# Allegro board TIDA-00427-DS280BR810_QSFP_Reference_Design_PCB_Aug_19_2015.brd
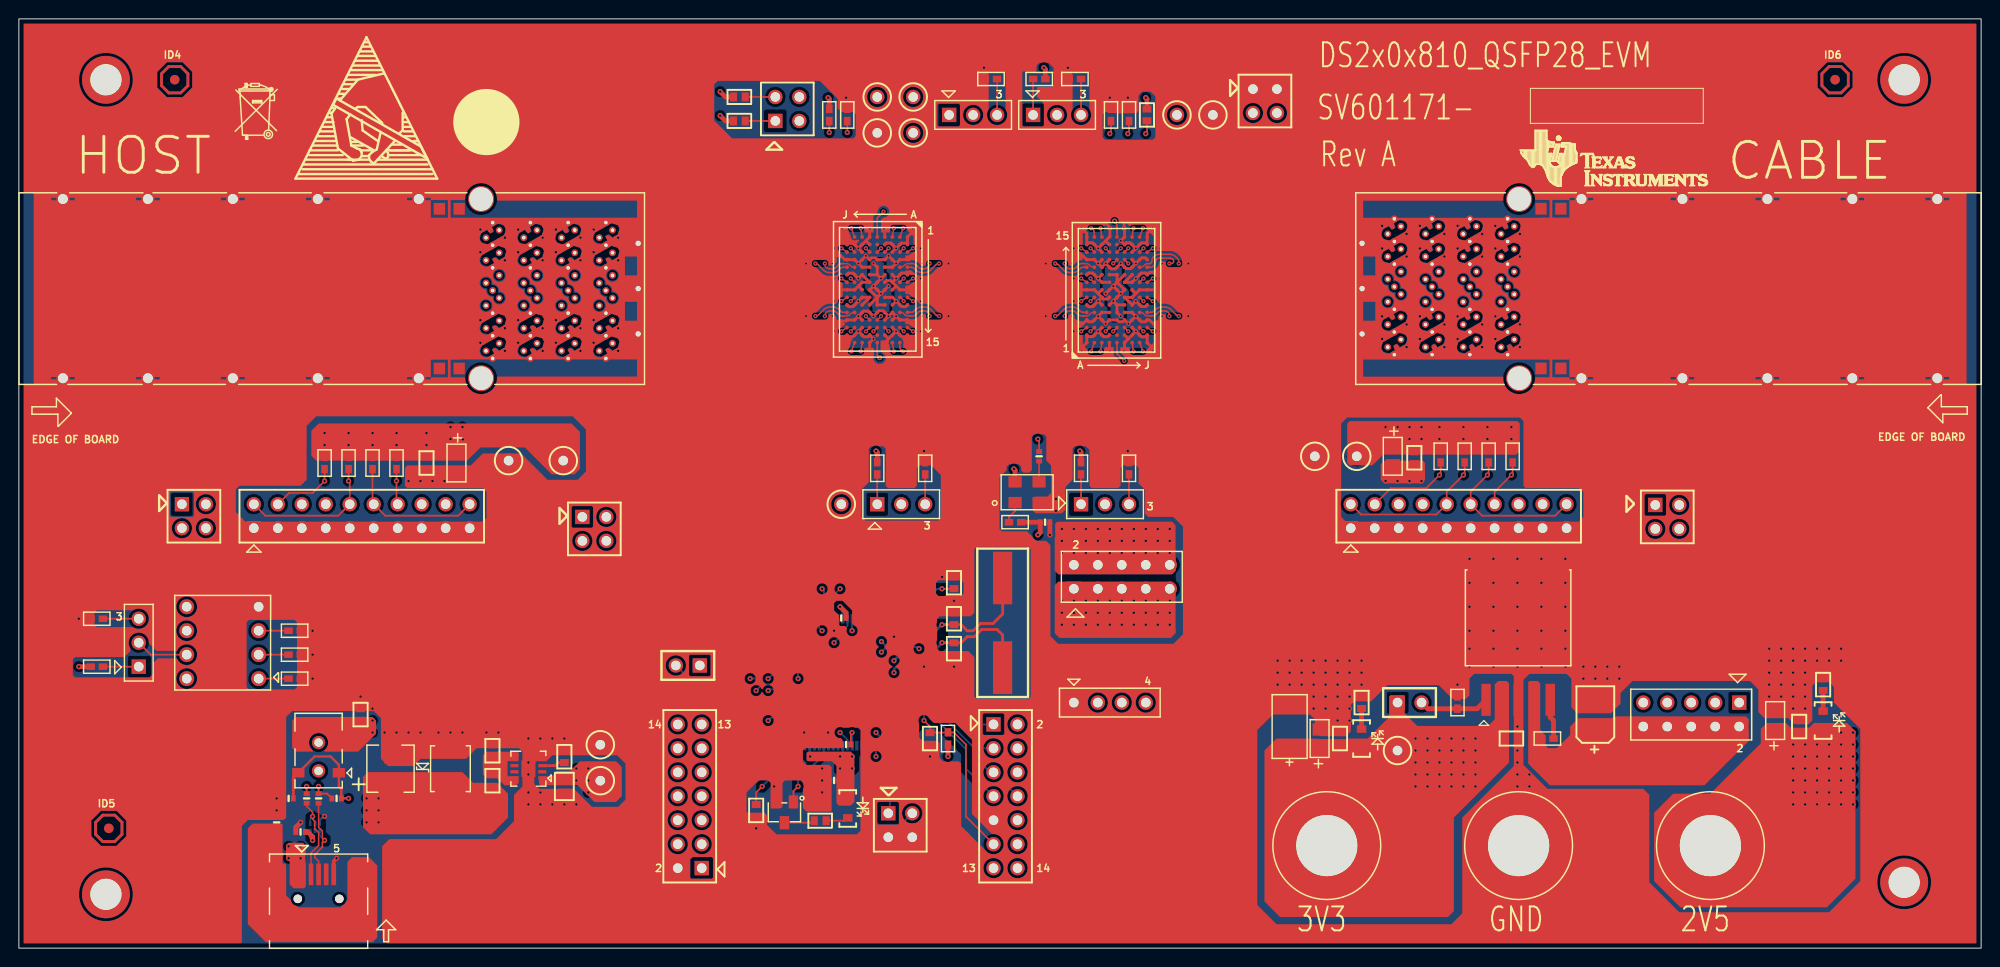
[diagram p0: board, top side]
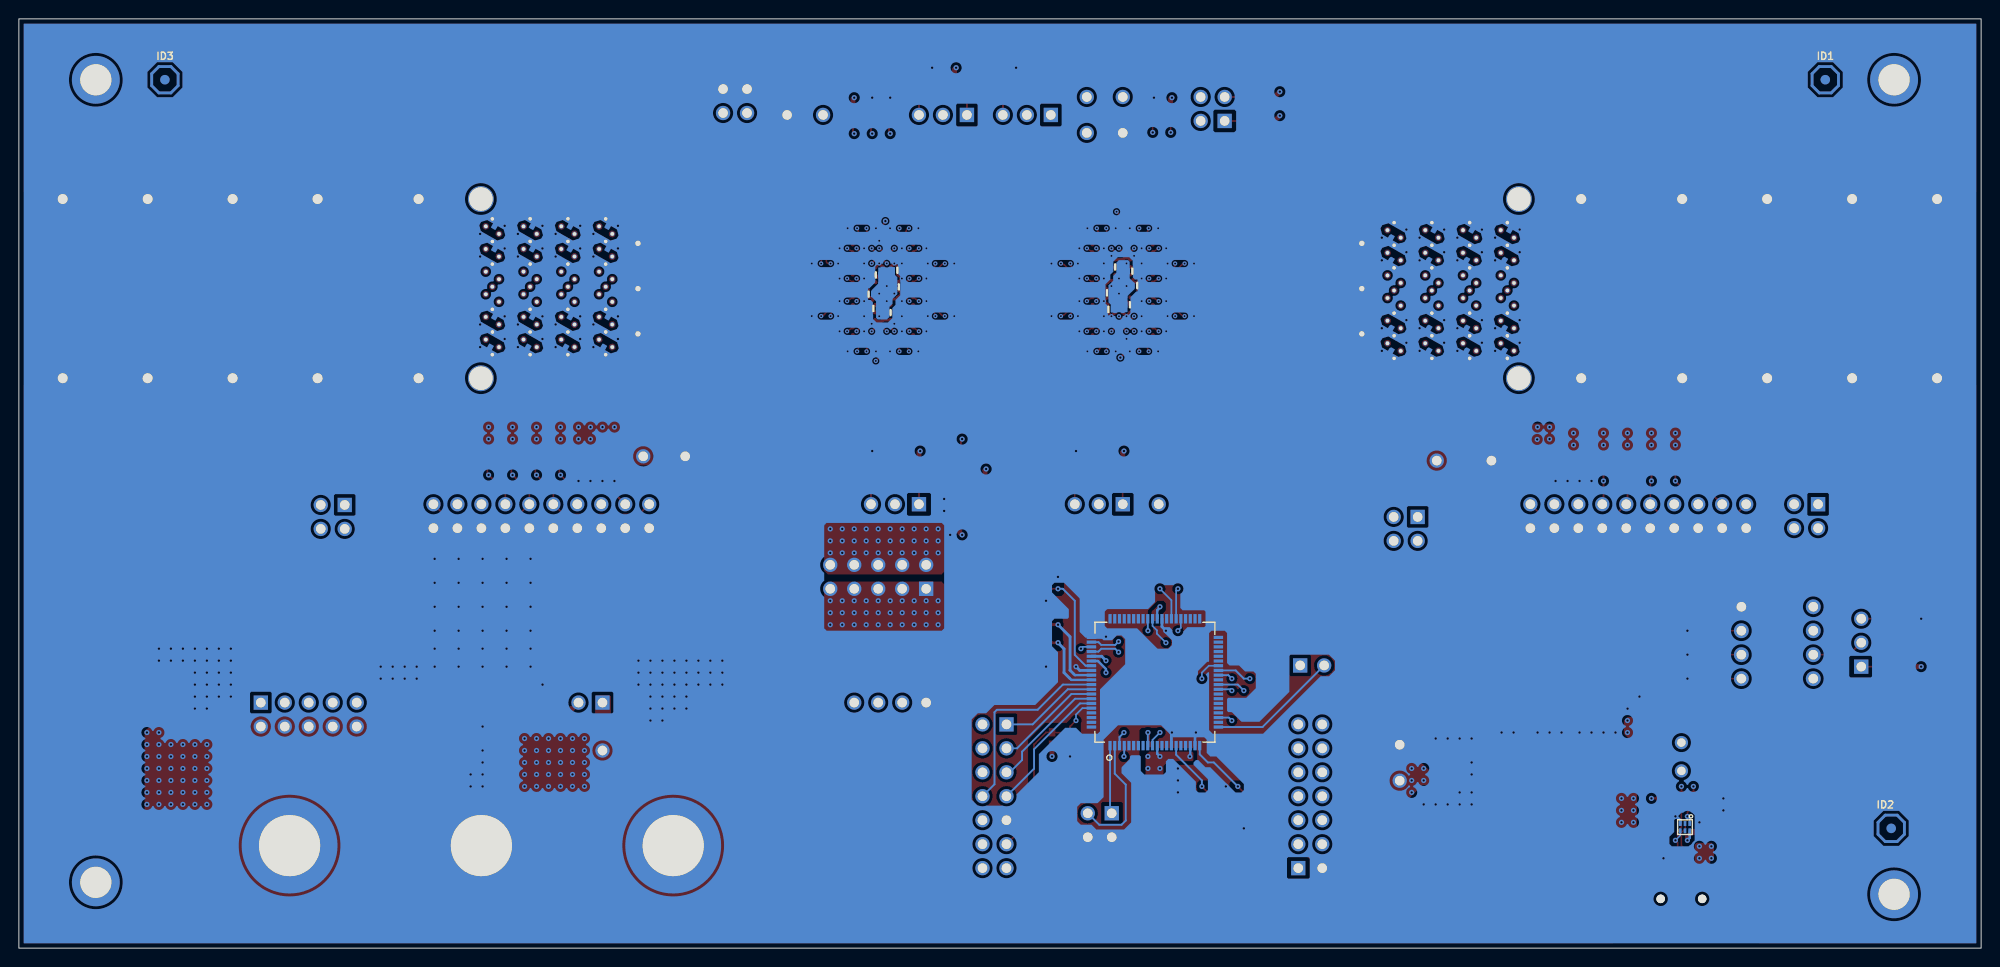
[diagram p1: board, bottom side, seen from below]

Outline 207.87 x 98.53 mm; copper layers: TOP, ART02, GND03, ART04, GND05, POWER06, POWER07, GND08, ART09, GND10, ART11, BOTTOM. Coordinates in mm from the lower left corner of the outline.
Outline path: rectangle 0,0 207.87,98.53

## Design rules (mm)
net group DIFF90: nets DM DP N16782058 N16782064 RXN0_CABLE_BOT RXN0_CABLE_TOP RXN0_HOST_BOT RXN0_HOST_TOP RXN1_CABLE_BOT RXN1_CABLE_TOP RXN1_HOST_BOT RXN1_HOST_TOP RXN2_CABLE_BOT RXN2_CABLE_TOP RXN2_HOST_BOT RXN2_HOST_TOP RXN3_CABLE_BOT RXN3_CABLE_TOP RXN3_HOST_BOT RXN3_HOST_TOP RXP0_CABLE_BOT RXP0_CABLE_TOP RXP0_HOST_BOT RXP0_HOST_TOP RXP1_CABLE_BOT RXP1_CABLE_TOP RXP1_HOST_BOT RXP1_HOST_TOP RXP2_CABLE_BOT RXP2_CABLE_TOP RXP2_HOST_BOT RXP2_HOST_TOP RXP3_CABLE_BOT RXP3_CABLE_TOP RXP3_HOST_BOT RXP3_HOST_TOP TXN0_CABLE_BOT TXN0_CABLE_TOP TXN0_HOST_BOT TXN0_HOST_TOP TXN1_CABLE_BOT TXN1_CABLE_TOP TXN1_HOST_BOT TXN1_HOST_TOP TXN2_CABLE_BOT TXN2_CABLE_TOP TXN2_HOST_BOT TXN2_HOST_TOP TXN3_CABLE_BOT TXN3_CABLE_TOP TXN3_HOST_BOT TXN3_HOST_TOP TXP0_CABLE_BOT TXP0_CABLE_TOP TXP0_HOST_BOT TXP0_HOST_TOP TXP1_CABLE_BOT TXP1_CABLE_TOP TXP1_HOST_BOT TXP1_HOST_TOP TXP2_CABLE_BOT TXP2_CABLE_TOP TXP2_HOST_BOT TXP2_HOST_TOP TXP3_CABLE_BOT TXP3_CABLE_TOP TXP3_HOST_BOT TXP3_HOST_TOP
net group POWER: nets GND N16782035 QSFP_VCC_3P3V VBUS VDD_2P5V VDD_2P5V_REG VDD_2P5V_REG_ENABLE_ VDD_3P3V VDD_3P3V_USB

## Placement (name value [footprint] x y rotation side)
C1  0.1 uF  [C_0402]  90.17 68.22 0 bottom
C2  0.1 uF  [C_0402]  89.92 71.78 0 bottom
C3  0.1 uF  [C_0402]  89.41 70.26 0 bottom
C4  0.1 uF  [C_0402]  91.74 72.22 180 bottom
C14  1 uF  [C_0402]  92.46 67.72 180 bottom
C15  0.1 uF  [C_0402]  114.65 70.11 0 bottom
C16  0.1 uF  [C_0402]  117.86 69.34 180 bottom
C17  0.1 uF  [C_0402]  115.53 67.38 0 bottom
C18  0.1 uF  [C_0402]  117.09 71.37 180 bottom
C28  1 uF  [C_0402]  117.35 67.82 180 bottom
C29  0.1 uF  [C_0402]  87.63 21.59 0 top
C30  2.2 nF  [C_0603]  96.52 22.23 270 top
C31  30 pF  [C_0603]  99.06 31.75 90 top
C32  30 pF  [C_0603]  99.06 34.92 270 top
C33  0.1 uF  [C_0402]  87.12 35 0 top
C34  0.47 uF  [C_0603]  78.11 14.61 270 top
C35  0.1 uF  [C_0402]  86.36 17.78 0 top
C36  0.1 uF  [C_0402]  29.84 12.32 0 top
C37  220 pF  [C_0603]  36.2 24.77 270 top
C38  22 uF  [CODE_B]  39.37 19.02 0 top
C39  1 uF  [C_0603]  50.16 20.93 270 top
C40  0.01 uF  [C_0603]  57.78 20.29 270 top
C41  2.2 uF  [C_0805]  57.78 17.14 90 top
C42  220 pF  [C_0603]  99.06 38.73 270 top
C43  0.1 uF  [C_0402]  108.71 45.16 180 top
C44  1 uF  [C_0603]  158.12 22.23 180 top
C45  47 uF  [C_1210]  167 24.77 90 top
C46  10 uF  [C_0805_TANT]  137.79 22.23 90 top
C47  1 uF  [C_0603]  139.95 22.23 270 top
C48  22 uF  [C_SIZEC]  134.62 23.5 90 top
C49  10 uF  [C_0805_TANT]  186.06 24.13 90 top
C50  1 uF  [C_0603]  188.59 23.5 90 top
C51  1 uF  [C_0603]  43.18 51.44 90 top
C52  10 uF  [C_0805_TANT]  46.35 51.44 270 top
C53  10 uF  [C_0805_TANT]  145.54 52.15 270 top
C54  1 uF  [C_0603]  147.83 51.99 90 top
C55  1 uF  [C_0402]  92.61 69.48 180 bottom
C56  1 uF  [C_0402]  114.81 71.88 0 bottom
D1  RED-LED  [LED_FOOTPRINT]  87.81 14.81 270 top
D2  1SMB5922BTS  [SMB]  45.72 19.02 90 top
D3  RED-LED  [LED_FOOTPRINT]  142.24 22.23 90 top
D4  RED-LED  [LED_FOOTPRINT]  191.13 24.13 90 top
FB1  BK1608HS600-T  [FB0603]  50.16 17.75 90 top
J1  HEADER 2X2  [HEADER_2X2]  92.1 14.3 270 top
J2  HEADER 7X2  [HEADER_7X2]  103.25 23.72 270 top
J3  HEADER 2X2  [HEADER_2X2]  59.69 45.72 270 top
J4  HEADER 1x4  [4_HEADER]  115.57 26.04 0 top
J5  HEADER 1x2  [CN-HDR1X2]  72.14 29.97 180 top
J6  USB_Conn_1734035-2  [1734035-2]  31.75 -0.03 0 top
J7  HEADER 5x2/SM_1  [CN-HDR2X5]  116.84 39.37 0 top
J8  HEADER, 2-PIN  [CN-HDR1X2]  146.05 26.04 0 top
J9  Binding Post, Keystone 7007, Black  [CN-BANANAJK-275-INTERFACE]  158.88 10.87 0 top
J10  Binding Post, Keystone 7006, Red  [CN-BANANAJK]  138.56 10.87 0 top
J11  Binding Post, Keystone 7006, Red  [CN-BANANAJK]  179.2 10.87 0 top
J12  HEADER 5x2/SM_1  [CN-HDR2X5]  177.16 24.77 180 top
J13  HEADER 10x2/SM  [HEADER_10X2_SM]  24.89 44.53 0 top
J14  HEADER 10x2/SM  [HEADER_10X2_SM]  141.1 44.53 0 top
J15  HEADER 7X2  [HEADER_7X2]  72.34 8.48 90 top
J16  HEADER 3  [3_HEADER]  109.98 88.34 0 top
J17  HEADER 3  [3_HEADER]  101.09 88.34 0 top
J18  4808-3004-CP  [DIP8]  21.59 32.38 90 top
J19  HEADER 3  [3_HEADER]  12.7 32.38 90 top
J20  HEADER 3  [3_HEADER]  93.47 47.07 0 top
J21  HEADER 3  [3_HEADER]  115.06 47.07 0 top
J22  HEADER 2X2  [HEADER_2X2]  80.14 87.71 0 top
J23  HEADER 2X2  [HEADER_2X2]  17.27 47.07 270 top
J24  HEADER 2X2  [HEADER_2X2]  173.35 46.99 270 top
J25  HEADER 2X2  [HEADER_2X2]  130.73 91.08 270 top
NOREF  -  []  37.33 86.03 0 top
NOREF#2  VAL ASSEMBLY  [unnamed#2]  9.22 5.71 0 top
NOREF#3  VAL ASSEMBLY  [unnamed#2]  199.72 92.07 0 top
NOREF#4  -  [unnamed#3]  192.41 92.08 0 top
NOREF#5  -  []  50.03 87.81 0 top
NOREF#6  -  []  27.68 88.83 0 top
NOREF#7  VAL ASSEMBLY  [unnamed#2]  199.72 6.98 0 top
NOREF#8  -  [unnamed#3]  16.51 92.08 0 top
NOREF#9  -  []  -137.59 -162.88 0 top
NOREF#10  VAL ASSEMBLY  [unnamed#2]  9.22 92.07 0 top
NOREF#11  -  [unnamed#3]  9.53 12.7 0 top
NOREF#12  -  [unnamed#3]  16.51 92.08 180 bottom
NOREF#13  -  [unnamed#3]  192.41 92.08 180 bottom
NOREF#14  -  [unnamed#3]  9.53 12.7 180 bottom
Q1  BSS138  [SOT-23]  81.1 14.4 180 top
R7  1k  [0402]  115.7 88.34 270 top
R8  1k  [0402]  117.6 88.34 270 top
R11  1k  [0402]  108.09 92.15 0 top
R12  2.0K  [RR0603]  119.51 88.34 270 top
R15  2.0K  [RR0603]  76.33 87.71 180 top
R19  1k  [0402]  111.87 92.15 0 top
R22  2.0K  [RR0603]  76.33 90.25 180 top
R23  1k  [0402]  87.76 88.34 270 top
R24  1k  [0402]  85.85 88.34 270 top
R25  33 k  [R_0402]  98.42 22.23 270 top
R26  200  [RES_HDC-0603]  84.89 13.51 180 top
R27  1k  [0402]  29.21 33.66 180 top
R28  33  [RES_HDC-0402]  30.48 15.88 90 top
R29  33  [RES_HDC-0402]  31.75 15.88 90 top
R30  1.5K  [RES_HDC-0402]  33.66 15.88 0 top
R31  33K  [RES_HDC-0402]  27.3 13.34 90 top
R32  1.2M  [RES_HDC-0402]  28.57 15.88 0 top
R33  4.7K  [R_0402]  105.54 45.16 0 top
R34  33  [RES_HDC-0402]  108.08 52.15 90 top
R35  10K  [R_0402]  152.4 26.04 90 top
R36  10K  [R_0402]  161.93 22.23 0 top
R37  750  [RES_HDC-0603]  142.24 26.04 90 top
R38  360  [RES_HDC-0603]  191.13 27.94 270 top
R39  4.7K  [R_0402]  40.01 51.44 90 top
R40  4.7K  [R_0402]  37.47 51.44 90 top
R41  4.7K  [R_0402]  32.38 51.44 90 top
R42  4.7K  [R_0402]  34.92 51.44 90 top
R43  4.7K  [R_0402]  158.24 52.15 90 top
R44  4.7K  [R_0402]  155.7 52.15 90 top
R45  4.7K  [R_0402]  150.62 52.15 90 top
R46  4.7K  [R_0402]  153.16 52.15 90 top
R47  1k  [0402]  102.98 92.15 0 top
R48  1k  [0402]  29.21 31.11 180 top
R49  1k  [0402]  29.21 28.57 180 top
R50  1k  [0402]  8.26 29.84 180 top
R51  1k  [0402]  8.26 34.92 0 top
R52  1k  [0402]  90.93 50.88 90 top
R53  1k  [0402]  96.01 50.88 270 top
R54  1k  [0402]  112.52 50.88 90 top
R55  1k  [0402]  117.6 50.88 270 top
S1  -  [EVQPSD02K]  31.75 20.29 90 top
TP1  TEST POINT  [0_100X0_100_INCH]  122.68 88.34 0 top
TP2  TEST POINT  [0_100X0_100_INCH]  126.49 88.34 0 top
TP3  TEST POINT  [0_100X0_100_INCH]  94.74 90.25 0 top
TP4  TEST POINT  [0_100X0_100_INCH]  94.74 86.44 90 top
TP5  TEST POINT  [0_100X0_100_INCH]  90.93 86.44 90 top
TP7  TEST POINT  [0_100X0_100_INCH]  90.93 90.25 0 top
TP8  TEST POINT  [0_100X0_100_INCH]  61.59 17.75 0 top
TP9  TEST POINT  [0_100X0_100_INCH]  61.59 21.56 0 top
TP10  TEST POINT  [0_100X0_100_INCH]  146.05 20.95 90 top
TP11  TEST POINT  [0_100X0_100INCH]  57.67 51.69 270 top
TP12  TEST POINT  [0_100X0_100INCH]  51.88 51.69 270 top
TP13  TEST POINT  [0_100X0_100INCH]  141.73 52.15 90 top
TP14  TEST POINT  [0_100X0_100INCH]  137.29 52.15 90 top
TP15  TEST POINT  [0_100X0_100_INCH]  87.12 47.07 0 top
U1  DS280BR8xx_DS280DF8xx  [DS280BR8XX_DS280DF8XX]  90.93 69.8 270 top
U2  DS280BR8xx_DS280DF8xx  [DS280BR8XX_DS280DF8XX]  116.33 69.8 90 top
U3  Value  [PN80]  87.53 28.19 180 bottom
U4  TPD4E004DRY  [SON-6]  31.37 12.83 0 bottom
U5  TPS73533DRB  [SON-8]  53.98 19.02 90 top
U6  Oscillator, 25 MHz, 2.5V  [TXC_2V5_OSC]  106.81 48.34 0 top
U7  TPS75725  [TO-263]  158.83 31.62 0 top
U8  TE_QSFP28_cage  [MOLEX_ZQSFP_CAGE]  33.15 69.93 0 top
U9  TE_QSFP28_cage  [MOLEX_ZQSFP_CAGE]  174.75 69.93 180 top
Y1  24.0 MHz  [HC49_US]  104.22 34.49 270 top

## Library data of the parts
C1-C4 C14-C18 C28 C29 C33 C35 C36 C43 C55 C56 = C_0402
C30-C32 C34 C37 C39 C40 C42 C44 C47 C50 C51 C54 = C_0603
C38 = CODE_B
C41 = C_0805
C45 = C_1210
C46 C49 C52 C53 = C_0805_TANT
C48 = C_SIZEC
D1 D3 D4 = LED_FOOTPRINT
D2 = SMB
FB1 = FB0603
J1 J3 J22-J25 = HEADER_2X2
J2 J15 = HEADER_7X2
J4 = 4_HEADER
J5 J8 = CN-HDR1X2
J6 = 1734035-2
J7 J12 = CN-HDR2X5
J9 = CN-BANANAJK-275-INTERFACE
J10 J11 = CN-BANANAJK
J13 J14 = HEADER_10X2_SM
J16 J17 J19-J21 = 3_HEADER
J18 = DIP8
Q1 = SOT-23
R7 R8 R11 R19 R23 R24 R27 R47-R55 = 0402
R12 R15 R22 = RR0603
R25 R33 R35 R36 R39-R46 = R_0402
R26 R37 R38 = RES_HDC-0603
R28-R32 R34 = RES_HDC-0402
S1 = EVQPSD02K
TP1-TP5 TP7-TP10 TP15 = 0_100X0_100_INCH
TP11-TP14 = 0_100X0_100INCH
U1 U2 = DS280BR8XX_DS280DF8XX
U3 = PN80
U4 = SON-6
U5 = SON-8
U6 = TXC_2V5_OSC
U7 = TO-263
U8 U9 = MOLEX_ZQSFP_CAGE
Y1 = HC49_US

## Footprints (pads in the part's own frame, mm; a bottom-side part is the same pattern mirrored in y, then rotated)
0_100X0_100_INCH
  round 1.524 hole 1.016: 1(0,0)
0_100X0_100INCH
  round 1.524 hole 1.016: 1(0,0)
3_HEADER
  rect 1.524x1.524 hole 1.016: 1(-2.54,0)
  round 1.524 hole 1.016: 2(0,0) 3(2.54,0)
4_HEADER
  rect 1.524x1.524 hole 1.016: 1(-3.81,0)
  round 1.524 hole 1.016: 2(-1.27,0) 3(1.27,0) 4(3.81,0)
0402
  rect 0.9x0.7 smd: 1(-0.65,0) 2(0.65,0)
1734035-2
  round 0.9 hole 0.9 unplated: (-2.2,5.25) (2.2,5.25)
  rect 0.5x2.3 smd: 1(-1.6,7.85) 2(-0.8,7.85) 3(0,7.85) 4(0.8,7.85) 5(1.6,7.85)
  rect 2x2.5 smd: 6(-4.45,7.75) 7(-4.45,2.25) 8(4.45,2.25) 9(4.45,7.75)
C_0402
  rect 0.508x0.635 smd: 1(-0.508,0) 2(0.508,0)
C_0603
  rect 0.749x0.95 smd: 1(-0.625,0) 2(0.625,0)
C_0805
  rect 1x1.45 smd: 1(-0.725,0) 2(0.725,0)
C_0805_TANT
  rect 1.3x1.501 smd: 1(-0.95,0) 2(0.95,0)
C_1210
  rect 2x2.2 smd: 1(-1.5,0) 2(1.5,0)
C_SIZEC
  rect 1.8x2.708 smd: 1(-2.3,0) 2(2.3,0)
CN-BANANAJK
  round 10.16 hole 6.477: 1(0,0)
CN-BANANAJK-275-INTERFACE
  round 10.16 hole 6.477: 1(0,0)
CN-HDR1X2
  rect 1.524x1.524 hole 1.016: 1(0,0)
  round 1.524 hole 1.016: 2(2.54,0)
CN-HDR2X5
  rect 1.524x1.524 hole 1.016: 1(-5.08,-1.27)
  round 1.524 hole 1.016: 2(-5.08,1.27) 3(-2.54,-1.27) 4(-2.54,1.27) 5(0,-1.27) 6(0,1.27) 7(2.54,-1.27) 8(2.54,1.27) 9(5.08,-1.27) 10(5.08,1.27)
CODE_B
  rect 1.27x2.5 smd: 1(0,-1.75) 2(0,1.75)
DIP8
  round 1.584 hole 1.016: 1(-3.81,-3.81) 2(-1.27,-3.81) 3(1.27,-3.81) 4(3.81,-3.81) 5(3.81,3.81) 6(1.27,3.81) 7(-1.27,3.81) 8(-3.81,3.81)
DS280BR8XX_DS280DF8XX
  round 0.408 smd: A1(-5.6,3.2) A2(-4.8,3.2) A3(-4,3.2) A4(-3.2,3.2) A5(-2.4,3.2) A6(-1.6,3.2) A7(-0.8,3.2) A8(0,3.2) A9(0.8,3.2) A10(1.6,3.2) A11(2.4,3.2) A12(3.2,3.2) A13(4,3.2) A14(4.8,3.2) A15(5.6,3.2) B1(-5.6,2.4) B2(-4.8,2.4) B3(-4,2.4) B4(-3.2,2.4) B5(-2.4,2.4) B6(-1.6,2.4) B7(-0.8,2.4) B8(0,2.4) B9(0.8,2.4) B10(1.6,2.4) B11(2.4,2.4) B12(3.2,2.4) B13(4,2.4) B14(4.8,2.4) B15(5.6,2.4) C1(-5.6,1.6) C2(-4.8,1.6) C3(-4,1.6) C4(-3.2,1.6) C5(-2.4,1.6) C6(-1.6,1.6) C7(-0.8,1.6) C8(0,1.6) C9(0.8,1.6) C10(1.6,1.6) C11(2.4,1.6) C12(3.2,1.6) C13(4,1.6) C14(4.8,1.6) C15(5.6,1.6) D1(-5.6,0.8) D2(-4.8,0.8) D3(-4,0.8) D4(-3.2,0.8) D5(-2.4,0.8) D6(-1.6,0.8) D7(-0.8,0.8) D8(0,0.8) D9(0.8,0.8) D10(1.6,0.8) D11(2.4,0.8) D12(3.2,0.8) D13(4,0.8) D14(4.8,0.8) D15(5.6,0.8) E1(-5.6,0) E2(-4.8,0) E3(-4,0) E4(-3.2,0) E5(-2.4,0) E6(-1.6,0) E7(-0.8,0) E8(0,0) E9(0.8,0) E10(1.6,0) E11(2.4,0) E12(3.2,0) E13(4,0) E14(4.8,0) E15(5.6,0) F1(-5.6,-0.8) F2(-4.8,-0.8) F3(-4,-0.8) F4(-3.2,-0.8) F5(-2.4,-0.8) F6(-1.6,-0.8) F7(-0.8,-0.8) F8(0,-0.8) F9(0.8,-0.8) F10(1.6,-0.8) F11(2.4,-0.8) F12(3.2,-0.8) F13(4,-0.8) F14(4.8,-0.8) F15(5.6,-0.8) G1(-5.6,-1.6) G2(-4.8,-1.6) G3(-4,-1.6) G4(-3.2,-1.6) G5(-2.4,-1.6) G6(-1.6,-1.6) G7(-0.8,-1.6) G8(0,-1.6) G9(0.8,-1.6) G10(1.6,-1.6) G11(2.4,-1.6) G12(3.2,-1.6) G13(4,-1.6) G14(4.8,-1.6) G15(5.6,-1.6) H1(-5.6,-2.4) H2(-4.8,-2.4) H3(-4,-2.4) H4(-3.2,-2.4) H5(-2.4,-2.4) H6(-1.6,-2.4) H7(-0.8,-2.4) H8(0,-2.4) H9(0.8,-2.4) H10(1.6,-2.4) H11(2.4,-2.4) H12(3.2,-2.4) H13(4,-2.4) H14(4.8,-2.4) H15(5.6,-2.4) J1(-5.6,-3.2) J2(-4.8,-3.2) J3(-4,-3.2) J4(-3.2,-3.2) J5(-2.4,-3.2) J6(-1.6,-3.2) J7(-0.8,-3.2) J8(0,-3.2) J9(0.8,-3.2) J10(1.6,-3.2) J11(2.4,-3.2) J12(3.2,-3.2) J13(4,-3.2) J14(4.8,-3.2) J15(5.6,-3.2)
EVQPSD02K
  round 1.408 hole 0.9 unplated: (-1.5,0) (1.5,0)
  rect 1x1.3 smd: 1(-1.7,-2.15) 2(1.7,-2.15) 3(-1.7,2.15) 4(1.7,2.15)
FB0603
  rect 0.749x0.95 smd: 1(-0.625,0) 2(0.625,0)
HC49_US
  rect 5.588x2.032 smd: 1(-4.75,0) 2(4.75,0)
HEADER_2X2
  rect 1.524x1.524 hole 1.016: 1(0,0)
  round 1.524 hole 1.016: 2(0,2.54) 3(2.54,0) 4(2.54,2.54)
HEADER_7X2
  rect 1.524x1.524 hole 1.016: 1(0,0)
  round 1.524 hole 1.016: 2(0,2.54) 3(2.54,0) 4(2.54,2.54) 5(5.08,0) 6(5.08,2.54) 7(7.62,0) 8(7.62,2.54) 9(10.16,0) 10(10.16,2.54) 11(12.7,0) 12(12.7,2.54) 13(15.24,0) 14(15.24,2.54)
HEADER_10X2_SM
  rect 1.524x1.524 hole 1.016: 1(0,0)
  round 1.524 hole 1.016: 2(0,2.54) 3(2.54,0) 4(2.54,2.54) 5(5.08,0) 6(5.08,2.54) 7(7.62,0) 8(7.62,2.54) 9(10.16,0) 10(10.16,2.54) 11(12.7,0) 12(12.7,2.54) 13(15.24,0) 14(15.24,2.54) 15(17.78,0) 16(17.78,2.54) 17(20.32,0) 18(20.32,2.54) 19(22.86,0) 20(22.86,2.54)
LED_FOOTPRINT
  rect 0.8x1 smd: 1(-1,0) 2(1,0)
MOLEX_ZQSFP_CAGE
  rect 1.2x1.25 smd: (11.4,8.46) (11.4,-8.47) (13.5,8.46) (13.5,-8.47)
  round 2.754 hole 2.5: (15.82,9.5) (15.82,-9.5)
  round 1.304 hole 1.05: C1(-28.48,9.5) C2(-19.48,9.5) C3(-10.48,9.5) C4(-1.48,9.5) C5(9.22,9.5) C9(9.22,-9.5) C10(-1.48,-9.5) C11(-10.48,-9.5) C12(-19.48,-9.5) C13(-28.48,-9.5)
  round 1.068 hole 0.56: C6(32.46,4.8) C7(32.46,0) C8(32.46,-4.8)
  round 0.73 hole 0.37: L1(17.04,7) L2(17.74,6.2) L3(16.34,5.4) L4(17.04,4.6) L5(17.74,3.8) L6(16.34,3) L7(17.04,2.2) L8(17.74,1.4) L9(16.34,0.6) L10(17.04,-0.2) L11(17.74,-1) L12(16.34,-1.8) L13(17.04,-2.6) L14(17.74,-3.4) L15(16.34,-4.2) L16(17.04,-5) L17(17.74,-5.8) L18(16.34,-6.6) L19(17.04,-7.4) L20(21.04,-7.4) L21(20.34,-6.6) L22(21.74,-5.8) L23(21.04,-5) L24(20.34,-4.2) L25(21.74,-3.4) L26(21.04,-2.6) L27(20.34,-1.8) L28(21.74,-1) L29(21.04,-0.2) L30(20.34,0.6) L31(21.74,1.4) L32(21.04,2.2) L33(20.34,3) L34(21.74,3.8) L35(21.04,4.6) L36(20.34,5.4) L37(21.74,6.2) L38(21.04,7) U1(25.04,7) U2(25.74,6.2) U3(24.34,5.4) U4(25.04,4.6) U5(25.74,3.8) U6(24.34,3) U7(25.04,2.2) U8(25.74,1.4) U9(24.34,0.6) U10(25.04,-0.2) U11(25.74,-1) U12(24.34,-1.8) U13(25.04,-2.6) U14(25.74,-3.4) U15(24.34,-4.2) U16(25.04,-5) U17(25.74,-5.8) U18(24.34,-6.6) U19(25.04,-7.4) U20(29.04,-7.4) U21(28.34,-6.6) U22(29.74,-5.8) U23(29.04,-5) U24(28.34,-4.2) U25(29.74,-3.4) U26(29.04,-2.6) U27(28.34,-1.8) U28(29.74,-1) U29(29.04,-0.2) U30(28.34,0.6) U31(29.74,1.4) U32(29.04,2.2) U33(28.34,3) U34(29.74,3.8) U35(29.04,4.6) U36(28.34,5.4) U37(29.74,6.2) U38(29.04,7)
PN80
  rect 0.346x1.004 smd: 1(-4.75,-6.725) 2(-4.25,-6.725) 3(-3.75,-6.725) 4(-3.25,-6.725) 5(-2.75,-6.725) 6(-2.25,-6.725) 7(-1.75,-6.725) 8(-1.25,-6.725) 9(-0.75,-6.725) 10(-0.25,-6.725) 11(0.25,-6.725) 12(0.75,-6.725) 13(1.25,-6.725) 14(1.75,-6.725) 15(2.25,-6.725) 16(2.75,-6.725) 17(3.25,-6.725) 18(3.75,-6.725) 19(4.25,-6.725) 20(4.75,-6.725) 41(4.75,6.725) 42(4.25,6.725) 43(3.75,6.725) 44(3.25,6.725) 45(2.75,6.725) 46(2.25,6.725) 47(1.75,6.725) 48(1.25,6.725) 49(0.75,6.725) 50(0.25,6.725) 51(-0.25,6.725) 52(-0.75,6.725) 53(-1.25,6.725) 54(-1.75,6.725) 55(-2.25,6.725) 56(-2.75,6.725) 57(-3.25,6.725) 58(-3.75,6.725) 59(-4.25,6.725) 60(-4.75,6.725)
  rect 1.004x0.346 smd: 21(6.725,-4.75) 22(6.725,-4.25) 23(6.725,-3.75) 24(6.725,-3.25) 25(6.725,-2.75) 26(6.725,-2.25) 27(6.725,-1.75) 28(6.725,-1.25) 29(6.725,-0.75) 30(6.725,-0.25) 31(6.725,0.25) 32(6.725,0.75) 33(6.725,1.25) 34(6.725,1.75) 35(6.725,2.25) 36(6.725,2.75) 37(6.725,3.25) 38(6.725,3.75) 39(6.725,4.25) 40(6.725,4.75) 61(-6.725,4.75) 62(-6.725,4.25) 63(-6.725,3.75) 64(-6.725,3.25) 65(-6.725,2.75) 66(-6.725,2.25) 67(-6.725,1.75) 68(-6.725,1.25) 69(-6.725,0.75) 70(-6.725,0.25) 71(-6.725,-0.25) 72(-6.725,-0.75) 73(-6.725,-1.25) 74(-6.725,-1.75) 75(-6.725,-2.25) 76(-6.725,-2.75) 77(-6.725,-3.25) 78(-6.725,-3.75) 79(-6.725,-4.25) 80(-6.725,-4.75)
R_0402
  rect 0.9x0.7 smd: 1(-0.65,0) 2(0.65,0)
RES_HDC-0402
  rect 0.508x0.635 smd: 1(-0.508,0) 2(0.508,0)
RES_HDC-0603
  rect 0.749x0.95 smd: 1(-0.625,0) 2(0.625,0)
RR0603
  rect 0.749x0.95 smd: 1(-0.625,0) 2(0.625,0)
SMB
  rect 2.159x2.743 smd: 1(-2.21,0) 2(2.21,0)
SON-6
  rect 0.3x0.52 smd: 1(-0.5,-0.385) 2(0,-0.385) 3(0.5,-0.385) 4(0.5,0.385) 5(0,0.385) 6(-0.5,0.385)
SON-8
  rect 0.35x0.85 smd: 1(-0.975,-1.475) 2(-0.325,-1.475) 3(0.325,-1.475) 4(0.975,-1.475) 5(0.975,1.475) 6(0.325,1.475) 7(-0.325,1.475) 8(-0.975,1.475)
  custom 0.375x0.375 smd: 9(0,0)
SOT-23
  rect 1x1.4 smd: 1(-0.95,-1.1) 2(0,1.1) 3(0.95,-1.1)
TO-263
  rect 1x3.4 smd: 1(-3.4,-5.3) 2(-1.7,-5.3) 3(0,-5.3) 4(1.7,-5.3) 5(3.4,-5.3)
  rect 10.7x8.6 smd: 6(0,5.3)
TXC_2V5_OSC
  rect 1.4x1.2 smd: 1(-1.27,-1.1) 2(1.27,-1.1) 3(1.27,1.1) 4(-1.27,1.1)
unnamed#2
  round 5.08 hole 3.302: (0,0)
unnamed#3
  round 1.016 smd: 1(0,0)

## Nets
GND: C1.1 C2.1 C3.1 C4.1 C14.1 C15.1 C16.1 C17.1 C18.1 C28.1 C29.1 C30.2 C31.1 C32.1 C33.1 C34.2 C35.1 C36.1 C37.1 C38.2 C39.1 C40.1 C41.1 C42.1 C43.1 C44.1 C45.2 C46.2 C47.1 C48.2 C49.2 C50.2 C51.1 C52.2 C53.2 C54.1 C55.1 C56.1 D2.2 J1.3 J1.4 J2.9 J4.1 J6.5 J9.1 J13.1 J13.3 J13.5 J13.7 J13.9 J13.11 J13.13 J13.15 J13.17 J13.19 J14.1 J14.3 J14.5 J14.7 J14.9 J14.11 J14.13 J14.15 J14.17 J14.19 J15.2 J18.4 J25.1 J25.2 Q1.3 R7.1 R8.1 R19.1 R23.1 R27.1 R31.2 R32.1 R35.2 R37.2 R38.1 R47.1 R48.1 R49.1 R51.1 R53.1 R55.1 TP2.1 TP5.1 TP9.1 TP12.1 TP14.1 U1.A1 U1.A2 U1.A4 U1.A6 U1.A8 U1.A10 U1.A12 U1.A14 U1.A15 U1.B2 U1.B4 U1.B6 U1.B8 U1.B10 U1.B12 U1.B14 U1.C2 U1.C3 U1.C4 U1.C5 U1.C6 U1.C7 U1.C8 U1.C9 U1.C10 U1.C11 U1.C12 U1.C13 U1.C14 U1.D1 U1.D2 U1.D4 U1.D5 U1.D7 U1.D9 U1.D11 U1.D12 U1.D14 U1.D15 U1.E4 U1.E11 U1.F1 U1.F2 U1.F4 U1.F5 U1.F7 U1.F9 U1.F11 U1.F14 U1.F15 U1.G2 U1.G3 U1.G4 U1.G5 U1.G6 U1.G7 U1.G8 U1.G9 U1.G10 U1.G11 U1.G12 U1.G13 U1.G14 U1.H2 U1.H4 U1.H6 U1.H8 U1.H10 U1.H12 U1.H14 U1.J1 U1.J2 U1.J4 U1.J6 U1.J8 U1.J10 U1.J12 U1.J14 U1.J15 U2.A1 U2.A2 U2.A4 U2.A6 U2.A8 U2.A10 U2.A12 U2.A14 U2.A15 U2.B2 U2.B4 U2.B6 U2.B8 U2.B10 U2.B12 U2.B14 U2.C2 U2.C3 U2.C4 U2.C5 U2.C6 U2.C7 U2.C8 U2.C9 U2.C10 U2.C11 U2.C12 U2.C13 U2.C14 U2.D1 U2.D2 U2.D4 U2.D5 U2.D7 U2.D9 U2.D11 U2.D12 U2.D14 U2.D15 U2.E4 U2.E11 U2.F1 U2.F2 U2.F4 U2.F5 U2.F7 U2.F9 U2.F11 U2.F14 U2.F15 U2.G2 U2.G3 U2.G4 U2.G5 U2.G6 U2.G7 U2.G8 U2.G9 U2.G10 U2.G11 U2.G12 U2.G13 U2.G14 U2.H2 U2.H4 U2.H6 U2.H8 U2.H10 U2.H12 U2.H14 U2.J1 U2.J2 U2.J4 U2.J6 U2.J8 U2.J10 U2.J12 U2.J14 U2.J15 U3.14 U3.19 U3.49 U3.61 U3.68 U4.3 U5.4 U5.9 U6.2 U7.3 U7.6 U8.C1 U8.C2 U8.C3 U8.C4 U8.C5 U8.C6 U8.C7 U8.C8 U8.C9 U8.C10 U8.C11 U8.C12 U8.C13 U8.L1 U8.L4 U8.L7 U8.L13 U8.L16 U8.L19 U8.L20 U8.L23 U8.L26 U8.L32 U8.L35 U8.L38 U8.U1 U8.U4 U8.U7 U8.U13 U8.U16 U8.U19 U8.U20 U8.U23 U8.U26 U8.U32 U8.U35 U8.U38 U9.C1 U9.C2 U9.C3 U9.C4 U9.C5 U9.C6 U9.C7 U9.C8 U9.C9 U9.C10 U9.C11 U9.C12 U9.C13 U9.L1 U9.L4 U9.L7 U9.L13 U9.L16 U9.L19 U9.L20 U9.L23 U9.L26 U9.L32 U9.L35 U9.L38 U9.U1 U9.U4 U9.U7 U9.U13 U9.U16 U9.U19 U9.U20 U9.U23 U9.U26 U9.U32 U9.U35 U9.U38
V18: C42.2 U3.67
VBUS: C36.2 C38.1 D2.1 FB1.1 J6.1 U3.65 U4.6
VDD_2P5V: C1.2 C2.2 C3.2 C4.2 C14.2 C15.2 C16.2 C17.2 C18.2 C28.2 C43.2 C49.1 C50.1 C55.2 C56.2 D4.1 J11.1 J12.1 J12.3 J12.5 J12.7 J12.9 J18.8 R11.2 R12.1 R15.2 R22.2 R24.1 R33.2 R50.2 R52.2 R54.2 TP1.1 TP4.1 U1.D6 U1.D8 U1.D10 U1.E5 U1.E6 U1.E7 U1.E8 U1.E9 U1.E10 U1.F6 U1.F8 U1.F10 U2.D6 U2.D8 U2.D10 U2.E5 U2.E6 U2.E7 U2.E8 U2.E9 U2.E10 U2.F6 U2.F8 U2.F10 U6.4
VDD_2P5V_PG_: R36.2 U7.5
VDD_2P5V_REG: C45.1 J12.2 J12.4 J12.6 J12.8 J12.10 R36.1 U7.4
VDD_2P5V_REG_ENABLE_: J8.2 R35.1 U7.1
VDD_3P3V: C44.2 C46.1 C47.2 C48.1 D3.1 J7.1 J7.3 J7.5 J7.7 J7.9 J8.1 J10.1 TP10.1 U7.2
VDD_3P3V_USB: C33.2 C35.2 C41.2 D1.1 R25.2 TP8.1 U3.11 U3.18 U3.50 U5.1
ADDR0_1: R8.2 U1.D13
ADDR0_2: R24.2 U2.D13
ADDR1_1: R7.2 U1.E13
ADDR1_2: R23.2 U2.E13
AIN_B_0: J1.1 U3.1
AIN_B_1: J1.2 U3.2
ALL_DONE_N_1: J17.1 TP3.1 U1.D3
ALL_DONE_N_2: TP15.1 U2.D3
BOT_INTL_CABLE: J14.14 R43.1 U9.L28
BOT_INTL_HOST: J13.14 R39.1 U8.L28
BOT_LPMODE_CABLE: J14.18 U9.L31
BOT_LPMODE_HOST: J13.18 U8.L31
BOT_MODPRSL_CABLE: J14.12 J14.20 R44.1 U9.L27
BOT_MODPRSL_HOST: J13.12 J13.20 R40.1 U8.L27
BOT_MODSELL_CABLE: J14.16 U9.L8
BOT_MODSELL_HOST: J13.16 U8.L8
CAL_CLK_IN_1: R34.2 U1.E1
CAL_CLK_OUT_1: U1.E15 U2.E1
CAL_CLK_OUT_2: TP7.1 U2.E15
DM: R28.2 U3.64
DP: R29.2 R30.1 U3.62
EN_SMB_1: J21.2 U1.E3
EN_SMB_2: J20.2 U2.E3
GPIO0_I2C_SDA: J3.4 U3.46
GPIO1_I2C_SCL: J3.3 U3.47
GPIO2_SPI_SCLK: J15.13 U3.45
GPIO3_PWM2: J15.11 U3.33
GPIO4_UART_TXD: J15.9 U3.51
GPIO5_UART_RXD: J15.7 U3.52
GPIO6_PWM1: J15.5 U3.29
GPIO7_PWM0: J15.3 U3.23
GPIO8_ADC3: J15.1 U3.4
GPIO9_ADC2: J15.14 U3.3
GPIO10_VEREFN: J15.12 U3.10
GPIO11_VEREFP: C29.2 J15.10 U3.9
GPIO12_EFC0_CLOCK: J5.2 U3.21
INT_N: J5.1 R12.2 U1.F3 U2.F3
P2_1: J15.8 U3.30
P2_3: J15.6 U3.32
P2_5: J15.4 U3.34
PUR: R30.2 R32.2 S1.1 S1.3 U3.63
QSFP_RESETL_CABLE: J25.4 U9.L9 U9.U9
QSFP_RESETL_HOST: J25.3 U8.L9 U8.U9
QSFP_SCL_CABLE: J24.2 U9.L11 U9.U11
QSFP_SCL_HOST: J23.2 U8.L11 U8.U11
QSFP_SDA_CABLE: J24.1 U9.L12 U9.U12
QSFP_SDA_HOST: J23.1 U8.L12 U8.U12
QSFP_VCC_3P3V: C51.2 C52.1 C53.1 C54.2 J7.2 J7.4 J7.6 J7.8 J7.10 R39.2 R40.2 R41.2 R42.2 R43.2 R44.2 R45.2 R46.2 TP11.1 TP13.1 U8.L10 U8.L29 U8.L30 U8.U10 U8.U29 U8.U30 U9.L10 U9.L29 U9.L30 U9.U10 U9.U29 U9.U30
READ_EN_N_1: J16.2 U1.F13
READ_EN_N_2: J17.2 U2.F13
RXN0_CABLE_BOT: U1.B1 U9.L18
RXN0_CABLE_TOP: U1.A9 U9.U18
RXN0_HOST_BOT: U2.B1 U8.L18
RXN0_HOST_TOP: U2.A9 U8.U18
RXN1_CABLE_BOT: U1.A5 U9.L21
RXN1_CABLE_TOP: U1.A13 U9.U21
RXN1_HOST_BOT: U2.A5 U8.L21
RXN1_HOST_TOP: U2.A13 U8.U21
RXN2_CABLE_BOT: U1.A3 U9.L15
RXN2_CABLE_TOP: U1.A11 U9.U15
RXN2_HOST_BOT: U2.A3 U8.L15
RXN2_HOST_TOP: U2.A11 U8.U15
RXN3_CABLE_BOT: U1.A7 U9.L24
RXN3_CABLE_TOP: U1.B15 U9.U24
RXN3_HOST_BOT: U2.A7 U8.L24
RXN3_HOST_TOP: U2.B15 U8.U24
RXP0_CABLE_BOT: U1.C1 U9.L17
RXP0_CABLE_TOP: U1.B9 U9.U17
RXP0_HOST_BOT: U2.C1 U8.L17
RXP0_HOST_TOP: U2.B9 U8.U17
RXP1_CABLE_BOT: U1.B5 U9.L22
RXP1_CABLE_TOP: U1.B13 U9.U22
RXP1_HOST_BOT: U2.B5 U8.L22
RXP1_HOST_TOP: U2.B13 U8.U22
RXP2_CABLE_BOT: U1.B3 U9.L14
RXP2_CABLE_TOP: U1.B11 U9.U14
RXP2_HOST_BOT: U2.B3 U8.L14
RXP2_HOST_TOP: U2.B11 U8.U14
RXP3_CABLE_BOT: U1.B7 U9.L25
RXP3_CABLE_TOP: U1.C15 U9.U25
RXP3_HOST_BOT: U2.B7 U8.L25
RXP3_HOST_TOP: U2.C15 U8.U25
SCL: J3.1 J4.3 J18.6 J22.4 J23.4 J24.4 U1.F12 U2.F12
SDA: J3.2 J4.4 J18.5 J22.3 J23.3 J24.3 U1.E12 U2.E12
TOP_INTL_CABLE: J14.4 R45.1 U9.U28
TOP_INTL_HOST: J13.4 R41.1 U8.U28
TOP_LPMODE_CABLE: J14.8 U9.U31
TOP_LPMODE_HOST: J13.8 U8.U31
TOP_MODPRSL_CABLE: J14.2 J14.10 R46.1 U9.U27
TOP_MODPRSL_HOST: J13.2 J13.10 R42.1 U8.U27
TOP_MODSELL_CABLE: J14.6 U9.U8
TOP_MODSELL_HOST: J13.6 U8.U8
TXN0_CABLE_BOT: U2.H1 U9.L37
TXN0_CABLE_TOP: U2.J9 U9.U37
TXN0_HOST_BOT: U1.H1 U8.L37
TXN0_HOST_TOP: U1.J9 U8.U37
TXN1_CABLE_BOT: U2.J5 U9.L2
TXN1_CABLE_TOP: U2.J13 U9.U2
TXN1_HOST_BOT: U1.J5 U8.L2
TXN1_HOST_TOP: U1.J13 U8.U2
TXN2_CABLE_BOT: U2.J3 U9.L34
TXN2_CABLE_TOP: U2.J11 U9.U34
TXN2_HOST_BOT: U1.J3 U8.L34
TXN2_HOST_TOP: U1.J11 U8.U34
TXN3_CABLE_BOT: U2.J7 U9.L5
TXN3_CABLE_TOP: U2.H15 U9.U5
TXN3_HOST_BOT: U1.J7 U8.L5
TXN3_HOST_TOP: U1.H15 U8.U5
TXP0_CABLE_BOT: U2.G1 U9.L36
TXP0_CABLE_TOP: U2.H9 U9.U36
TXP0_HOST_BOT: U1.G1 U8.L36
TXP0_HOST_TOP: U1.H9 U8.U36
TXP1_CABLE_BOT: U2.H5 U9.L3
TXP1_CABLE_TOP: U2.H13 U9.U3
TXP1_HOST_BOT: U1.H5 U8.L3
TXP1_HOST_TOP: U1.H13 U8.U3
TXP2_CABLE_BOT: U2.H3 U9.L33
TXP2_CABLE_TOP: U2.H11 U9.U33
TXP2_HOST_BOT: U1.H3 U8.L33
TXP2_HOST_TOP: U1.H11 U8.U33
TXP3_CABLE_BOT: U2.H7 U9.L6
TXP3_CABLE_TOP: U2.G15 U9.U6
TXP3_HOST_BOT: U1.H7 U8.L6
TXP3_HOST_TOP: U1.G15 U8.U6
VUSB: C37.2 S1.2 S1.4 U3.66
WP: J18.7 J19.2
N16780616: C32.2 U3.69 Y1.1
N16780624: C31.2 U3.70 Y1.2
N16780665: J2.1 U3.72
N16780674: Q1.1 U3.15
N16780676: J2.8 U3.71
N16780680: J2.3 U3.73
N16780690: J2.5 U3.74
N16780698: J2.7 U3.75
N16780708: C30.1 J2.11 R25.1 U3.76
N16780744: D1.2 R26.1
N16780746: Q1.2 R26.2
N16780748: C34.1 U3.20
N16782035: J6.6 J6.7 J6.8 J6.9 R31.1
N16782058: J6.2 R28.1 U4.1
N16782064: J6.3 R29.1 U4.4
N16782665: C39.2 FB1.2 U5.5 U5.8
N16782724: C40.2 U5.3
N16869157: R33.1 U6.1
N16869235: R34.1 U6.3
N16899401: J16.1 R11.1
N16899406: J16.3 R19.2
N16899979: J17.3 R47.2
N16900523: J18.1 R49.2
N16900525: J18.2 R48.2
N16900527: J18.3 R27.2
N16901581: J19.1 R50.1
N16901585: J19.3 R51.2
N16901924: J20.1 R52.1
N16901939: J20.3 R53.2
N16902597: J21.1 R54.1
N16902612: J21.3 R55.2
N16903155: J22.2 R22.1
N16903160: J22.1 R15.1
N168714110: D3.2 R37.1
N168716471: D4.2 R38.2

Pads without a net: J2 2 4 6 10 12 13 14; J4 2; J6 4; NOREF#4 1; NOREF#8 1; NOREF#11 1; NOREF#12 1; NOREF#13 1; NOREF#14 1; U1 E2 E14; U2 E2 E14; U3 5 6 7 8 12 13 16 17 22 24 25 26 27 28 31 35 36 37 38 39 40 41 42 43 44 48 53 54 55 56 57 58 59 60 77 78 79 80; U4 2 5; U5 2 6 7

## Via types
v1: diameter 0.559, hole 0.254, TOP to BOTTOM, 474 vias
v2: diameter 0.457, hole 0.203, TOP to BOTTOM, 174 vias

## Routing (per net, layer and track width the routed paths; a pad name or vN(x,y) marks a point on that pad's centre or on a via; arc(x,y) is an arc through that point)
GND: length 194.8
  TOP w0.183: 115.55,62.5 115.59,62.53 ; 95.59,69.76 95.55,69.8 ; 112.59,63.65 v2(112.59,63.27) ; 111.72,69.8 111.68,69.84 ; 91.71,77.1 91.68,77.07
  TOP w0.305: U2.D7 115.36,68.82 114.91,68.82 U2.C7 ; U1.C7 92.36,70.78 91.91,70.78 U1.D7 ; U1.C7 v2(92.93,71) ; U1.C7 92.93,70.2 ; v2(92.93,71) U1.C6 ; v2(92.93,71) U1.B6 93.52,71.59 93.95,71.59 U1.A6 ; U1.G10 U1.F9 U1.G9 v2(88.93,68.6) U1.H10 88.34,68.01 87.92,68.01 U1.J10 ; v2(114.33,74.2) U2.C13 ; v2(114.33,74.2) U2.C14 115.11,74.98 ; v2(114.33,74.2) U2.B14 113.75,74.79 113.32,74.79 U2.A14 U2.A15 113.13,75.78 v2(112.59,76.33) ; v2(92.13,67) 92.53,67.4 U1.C11 v2(92.93,67) ; v2(92.13,67) U1.D12 ; v2(92.13,67) U1.D11 91.73,67.4 91.54,67.58 91.12,67.58 U1.E11 v2(90.53,67) U1.F11 89.98,67.55 89.48,67.55 U1.G11 v2(88.93,67) ; v2(92.93,67) U1.C12 ; v2(92.93,67) U1.B12 U1.A12 94.23,66.5 94.84,66.5 95.15,66.19 ; U2.D2 115.36,64.83 114.9,64.83 U2.C2 v2(114.33,65.4) ; 118.49,61.87 117.09,63.27 v2(117.08,63.27) arc(117.12,63.33) 117.13,63.4 U2.F1 117.53,64.6 ; 86.82,66.32 87,66.5 87.63,66.5 U1.J12 U1.H12 v2(88.93,67) ; v2(111.73,65.4) 111.73,65.92 111.98,66.17 112.7,66.17 U2.A4 113.32,66.41 113.74,66.41 U2.B4 v2(114.33,67) ; v2(114.33,72.6) U2.B12 U2.A12 112.75,73.38 112.06,73.38 ; v2(114.33,72.6) U2.C11 v2(115.13,72.6) ; v2(114.33,72.6) U2.C12 ; v2(114.33,67) U2.C4 v2(115.13,66.2) 115.53,66.6 U2.D4 U2.E4 116.51,66.42 116.95,66.42 U2.F4 117.13,66.6 v2(117.53,66.2) U2.G4 v2(118.33,67) ; v2(114.33,67) U2.C5 U2.D5 ; U1.C10 v2(92.93,68.6) ; v2(92.93,68.6) U1.C9 U1.D9 ; v2(92.93,68.6) U1.B10 93.52,68.01 93.95,68.01 U1.A10 ; U2.C10 v2(114.33,71) ; v2(114.33,71) U2.C9 U2.D9 ; v2(114.33,71) U2.B10 113.75,71.59 113.32,71.59 U2.A10 ; 117.53,64.6 U2.F2 ; 117.53,64.6 U2.G2 v2(118.33,65.4) ; 115.11,74.98 115.49,74.6 U2.D14 ; 115.11,74.98 U2.D15 115.59,75.45 v2(115.59,76.33) 115.59,76.43 114.62,77.39 ; v2(120.08,76.33) 119.53,75.78 U2.J15 U2.J14 119.35,74.79 118.92,74.79 U2.H14 v2(118.33,74.2) ; 118.33,69.4 U2.H8 U2.J8 120.9,69.8 120.92,69.82 ; 118.33,69.4 U2.G8 ; 118.33,69.4 U2.G7 U2.F7 U2.G6 v2(118.33,68.6) U2.H6 118.91,68.02 119.35,68.02 U2.J6 ; 116.96,77.36 117.08,77.24 v2(117.08,76.33) 117.13,76.27 U2.F15 v2(116.73,75) U2.F14 117.32,74.79 117.75,74.79 U2.G14 v2(118.33,74.2) ; v2(88.93,67) U1.G12 ; U1.D5 U1.C5 v2(92.93,72.6) ; 89.73,75 U1.F1 90.13,76.2 arc(90.15,76.27) v2(90.19,76.33) 90.17,76.33 88.77,77.72 ; 89.73,75 U1.F2 ; 89.73,75 U1.G2 v2(88.93,74.2) ; 115.59,62.53 v2(115.59,63.27) 115.53,63.33 U2.D1 ; v2(87.19,76.33) 87.19,75.95 U1.J1 U1.J2 87.92,74.79 88.34,74.79 U1.H2 v2(88.93,74.2) ; v2(118.33,74.2) U2.G13 ; v2(118.33,72.6) U2.G11 117.78,72.05 117.28,72.05 U2.F11 v2(116.73,72.6) U2.E11 116.15,72.01 115.72,72.01 115.54,72.2 U2.D11 v2(115.13,72.6) ; v2(118.33,72.6) U2.G12 ; v2(118.33,72.6) U2.H12 118.92,73.19 119.34,73.19 U2.J12 ; U1.C3 v2(92.93,74.2) ; v2(92.93,74.2) U1.B2 93.49,74.76 93.97,74.76 U1.A2 U1.A1 94.68,75.95 v2(94.68,76.33) ; v2(92.93,74.2) U1.C2 92.36,74.77 91.9,74.77 U1.D2 ; v2(120.08,63.27) 120.08,63.65 U2.J1 U2.J2 119.34,64.81 118.92,64.81 U2.H2 v2(118.33,65.4) ; U2.F5 U2.G5 v2(118.33,67) ; v2(88.93,74.2) U1.G3 ; v2(88.93,65.4) U1.H14 88.35,64.81 87.92,64.81 U1.J14 ; v2(88.93,65.4) U1.G13 ; v2(88.93,65.4) U1.G14 89.52,64.81 89.95,64.81 U1.F14 v2(90.53,64.6) U1.F15 90.13,63.33 v2(90.19,63.27) 90.19,62.36 90.31,62.24 ; v2(88.93,72.6) U1.G4 v2(89.73,73.4) U1.F4 90.31,73.18 90.75,73.18 U1.E4 U1.D4 v2(92.13,73.4) U1.C4 v2(92.93,72.6) ; v2(88.93,72.6) U1.G5 U1.F5 ; v2(88.93,72.6) U1.H4 U1.J4 87.49,73 87.07,73.42 86.06,73.42 86.04,73.4 ; U2.A6 113.32,68.01 113.75,68.01 U2.B6 v2(114.33,68.6) ; 95.55,69.8 U1.A8 U1.B8 92.93,70.2 ; v2(92.93,72.6) U1.B4 U1.A4 94.32,73 94.52,73.2 95.05,73.2 95.53,73.68 v2(95.53,74.2) ; v2(94.68,63.27) 94.13,63.82 U1.A15 U1.A14 93.95,64.81 93.52,64.81 U1.B14 v2(92.93,65.4) ; U1.D1 91.73,76.27 v2(91.68,76.33) 91.68,77.07 ; v2(118.33,65.4) U2.G3 ; v2(92.93,65.4) U1.C14 92.13,64.6 ; v2(92.93,65.4) U1.C13 ; 114.33,69.4 U2.C8 ; 114.33,69.4 U2.C7 ; 114.33,69.4 U2.B8 U2.A8 111.72,69.8 ; U2.C7 v2(114.33,68.6) ; U2.G10 U2.F9 U2.G9 v2(118.33,71) U2.H10 118.92,71.59 119.34,71.59 U2.J10 119.79,71.65 121.11,71.65 121.26,71.81 ; 92.93,70.2 U1.C8 ; U1.D14 92.13,64.6 ; 92.13,64.6 U1.D15 91.68,64.15 v2(91.68,63.27) 91.68,63.17 92.64,62.2 ; 121.22,66.19 121.21,66.18 120.2,66.18 119.78,66.6 U2.J4 119.34,66.41 118.92,66.41 U2.H4 v2(118.33,67) ; v2(114.33,68.6) U2.C6 ; v2(114.33,65.4) U2.C3 ; v2(114.33,65.4) U2.B2 113.77,64.84 113.29,64.84 U2.A2 U2.A1 112.59,63.65 ; v2(115.13,72.6) U2.D12 ; 88.93,70.2 U1.G7 U1.F7 U1.G6 v2(88.93,71) U1.H6 88.35,71.58 87.91,71.58 U1.J6 ; 88.93,70.2 U1.G8 ; 88.93,70.2 U1.H8 U1.J8 86.36,69.8 86.34,69.78
  TOP w0.381: v1(33.66,9.53) 33.35,9.22 J6.5
  TOP w0.508: v1(102.23,93.34) 102.33,93.25 R47.1 ; R53.1 96.01,52.58 v1(95.89,52.7) ; R32.1 v1(27.3,15.88) ; R48.1 v1(31.11,31.11) ; R49.1 v1(31.11,28.57) ; v1(109.22,43.81) C43.1 ; R55.1 117.6,52.58 v1(117.47,52.7) ; v1(29.84,13.34) 29.34,12.83 C36.1 ; v1(37.46,25.39) C37.1 v1(36.2,26.67) ; C30.2 v1(96.52,20.32) ; R51.1 v1(6.35,34.92) ; C34.2 v1(78.11,12.7) ; R27.1 v1(31.11,33.66) ; R31.2 v1(27.3,14.61)
  BOTTOM w0.254: 32.26,13.97 31.87,13.58 U4.3
  BOTTOM w0.279: v1(83.19,22.86) 83.28,22.77 U3.19
  BOTTOM w0.305: v1(92.71,33.02) 92.79,32.94 U3.61 ; v1(95.89,29.84) 95.48,29.44 U3.68 ; 32.26,13.97 v1(32.38,13.97) ; v1(85.72,22.86) 85.78,22.81 U3.14 ; U3.49 86.78,34.07 v1(86.36,33.66)
  vias: v1(38.73,22.86) v1(40.01,22.86) v1(41.27,49.53) v1(41.27,22.86) v1(42.55,49.53) v1(42.55,22.86) v1(43.81,49.53) v1(44.45,22.86) v1(45.09,49.53) v1(45.72,22.86) v1(46.99,22.86) v1(48.89,76.19) v1(48.89,73.79) v1(48.89,66.59) v1(48.89,64.19) v1(49.53,22.86) v1(50.8,22.86) v1(51.49,75.33) v1(51.49,72.93) v1(51.49,65.73) v1(51.49,63.33) v1(52.89,76.19) v1(52.89,73.79) v1(52.89,66.59) v1(52.89,64.19) v1(53.98,22.23) v1(53.98,19.68) v1(53.98,18.41) v1(53.98,16.51) v1(53.98,15.24) v1(55.24,22.23) v1(55.24,16.51) v1(55.24,15.24) v1(55.49,75.33) v1(55.49,72.93) v1(55.49,65.73) v1(55.49,63.33) v1(56.52,22.23) v1(56.52,15.24) v1(56.89,76.19) v1(56.89,73.79) v1(56.89,66.59) v1(56.89,64.19) v1(57.78,22.23) v1(57.78,15.24) v1(59.05,15.24) v1(59.49,75.33) v1(59.49,72.93) v1(59.49,65.73) v1(59.49,63.33) v1(60.89,76.19) v1(60.89,73.79) v1(60.89,66.59) v1(60.89,64.19) v1(63.49,75.33) v1(63.49,72.93) v1(63.49,65.73) v1(63.49,63.33) v1(80.01,17.14) v1(85.09,19.05) v1(85.09,17.78) v1(85.09,16.51) v1(87.63,90.17) v1(97.8,39.36) v1(99.06,36.83) v1(99.06,29.84) v1(109.86,47.62) v1(109.86,46.35) v1(111.12,93.34) v1(115.57,90.17) v1(117.47,90.17) v1(133.35,30.48) v1(133.35,29.21) v1(133.35,27.94) v1(134.62,30.48) v1(134.62,29.21) v1(134.62,27.94) v1(135.89,30.48) v1(135.89,29.21) v1(135.89,27.94) v1(137.16,30.48) v1(137.16,29.21) v1(137.16,27.94) v1(137.16,26.67) v1(137.16,25.4) v1(138.43,30.48) v1(138.43,29.21) v1(138.43,27.94) v1(138.43,26.67) v1(138.43,25.4) v1(139.7,30.48) v1(139.7,29.21) v1(139.7,27.94) v1(139.7,26.67) v1(139.7,25.4) v1(139.7,24.13) v1(140.97,30.48) v1(140.97,29.21) v1(140.97,27.94) v1(140.97,26.67) v1(140.97,25.4) v1(140.97,24.13) v1(142.24,30.48) v1(142.24,29.21) v1(142.24,27.94) v1(144.41,76.59) v1(144.41,74.19) v1(144.41,66.99) v1(144.41,64.59) v1(144.78,49.53) v1(146.05,49.53) v1(147.01,75.73) v1(147.01,73.33) v1(147.01,66.13) v1(147.01,63.73) v1(147.32,49.53) v1(148.41,76.59) v1(148.41,74.19) v1(148.41,66.99) v1(148.41,64.59) v1(148.59,49.53) v1(151.01,75.73) v1(151.01,73.33) v1(151.01,66.13) v1(151.01,63.73) v1(152.41,76.59) v1(152.41,74.19) v1(152.41,66.99) v1(152.41,64.59) v1(152.4,27.94) v1(153.67,41.27) v1(153.67,38.73) v1(153.67,36.2) v1(153.67,33.66) v1(153.67,31.75) v1(153.67,29.84) v1(155.01,75.73) v1(155.01,73.33) v1(155.01,66.13) v1(155.01,63.73) v1(156.21,41.27) v1(156.21,38.73) v1(156.21,36.2) v1(156.21,33.66) v1(156.21,31.75) v1(156.21,29.84) v1(156.41,76.59) v1(156.41,74.19) v1(156.41,66.99) v1(156.41,64.59) v1(158.75,41.27) v1(158.75,38.73) v1(158.75,36.2) v1(158.75,33.66) v1(158.75,31.75) v1(158.75,29.84) v1(158.75,23.5) v1(158.75,20.95) v1(158.75,19.68) v1(158.75,18.41) v1(158.75,17.14) v1(159.01,75.73) v1(159.01,73.33) v1(159.01,66.13) v1(159.01,63.73) v1(160.02,18.41) v1(160.02,17.14) v1(161.29,41.27) v1(161.29,38.73) v1(161.29,36.2) v1(161.29,33.66) v1(161.29,31.75) v1(161.29,29.84) v1(163.83,41.27) v1(163.83,38.73) v1(163.83,36.2) v1(163.83,33.66) v1(163.83,31.75) v1(163.83,29.84) v1(165.74,29.84) v1(165.74,28.57) v1(167,29.84) v1(167,28.57) v1(168.28,29.84) v1(168.28,28.57) v1(169.54,29.84) v1(169.54,28.57) v1(185.42,31.75) v1(185.42,30.48) v1(185.42,29.21) v1(185.42,27.94) v1(185.42,26.67) v1(186.69,31.75) v1(186.69,30.48) v1(186.69,29.21) v1(186.69,27.94) v1(186.69,26.67) v1(187.96,31.75) v1(187.96,30.48) v1(187.96,29.21) v1(187.96,27.94) v1(187.96,26.67) v1(187.96,25.4) v1(189.23,31.75) v1(189.23,30.48) v1(189.23,29.21) v1(189.23,27.94) v1(189.23,26.67) v1(189.23,25.4) v1(190.5,31.75) v1(190.5,30.48) v1(191.77,31.75) v1(191.77,30.48) v1(193.04,31.75) v1(193.04,30.48) v2(83.38,72.59) v2(83.38,67.01) v2(86.18,72.59) v2(86.18,67.01) v2(86.33,74.2) v2(86.33,71) v2(86.33,68.6) v2(86.33,65.4) v2(87.19,63.27) v2(95.53,71) v2(95.53,68.6) v2(95.53,65.4) v2(95.68,72.59) v2(95.68,67.01) v2(98.48,72.59) v2(98.48,67.01) v2(108.78,72.59) v2(108.78,67.01) v2(111.58,72.59) v2(111.58,67.01) v2(111.73,74.2) v2(111.73,71) v2(111.73,68.6) v2(120.93,74.2) v2(120.93,71) v2(120.93,68.6) v2(120.93,65.4) v2(121.08,72.59) v2(121.08,67.01) v2(123.88,72.59) v2(123.88,67.01)
V18: length 11.6
  TOP w0.183: v1(97.79,38.1) 99.05,38.1 C42.2
  BOTTOM w0.203: v1(97.79,38.1) 97.28,38.1 96.01,36.83 96.01,31.09 94.87,29.94 U3.67
VBUS: length 4.2
  TOP w0.508: v1(31.11,11.43) 31.11,11.81 30.61,12.32 C36.2
  BOTTOM w0.254: v1(31.11,11.43) 30.87,11.68 U4.6
  BOTTOM w0.305: v1(92.71,30.48) 93.17,30.94 U3.65
  vias: v1(28.57,10.79) v1(28.57,9.53) v1(29.84,10.79) v1(29.84,9.53) v1(36.83,15.88) v1(36.83,14.61) v1(36.83,13.34) v1(38.1,15.88) v1(38.1,14.61) v1(38.1,13.34)
VDD_2P5V: length 39
  TOP w0.305: U2.D10 U2.E10 U2.E9 ; v2(116.73,69.4) U2.E7 v2(115.93,68.6) ; v2(116.73,69.4) U2.E8 v2(115.93,70.2) ; v2(116.73,69.4) U2.F8 U2.E9 ; U2.E9 U2.F10 ; U2.E9 v2(115.93,70.2) ; v2(115.93,70.2) U2.D8 v2(115.13,69.4) ; U1.F6 U1.E6 ; U1.E6 v2(91.33,71) ; U1.E6 U1.E5 v2(90.53,72.6) ; v2(91.33,69.4) U1.D8 v2(92.13,70.2) ; v2(91.33,69.4) U1.E9 ; v2(91.33,69.4) U1.E8 90.53,70.2 v2(90.53,70.2) ; U2.E6 v2(115.93,68.6) ; U2.E6 U2.F6 ; U2.E6 U2.E5 v2(116.73,67) ; v2(115.93,68.6) U2.D6 ; U1.E9 U1.F10 ; U1.E9 U1.F8 v2(90.53,70.2) ; U1.E9 U1.E10 U1.D10 ; v2(90.53,70.2) U1.E7 v2(91.33,71) ; v2(91.33,71) U1.D6
  TOP w0.508: v1(108.58,93.34) 108.74,93.19 R11.2 ; R24.1 85.85,90.04 v1(85.72,90.17) ; R54.2 112.52,52.58 v1(112.39,52.7) ; v1(74.3,90.81) 74.85,90.25 R22.2 ; R50.2 v1(6.35,29.84) ; v1(74.3,88.27) 74.85,87.71 R15.2 ; v1(90.81,52.7) 90.93,52.58 R52.2 ; U6.4 105.54,50.67 v1(105.41,50.8) ; v1(119.38,90.17) 119.51,90.04 R12.1 ; R33.2 C43.2 108.2,44.07 v1(107.95,43.81)
  vias: v1(187.96,21.59) v1(187.96,20.32) v1(187.96,19.05) v1(187.96,17.78) v1(187.96,16.51) v1(187.96,15.24) v1(189.23,21.59) v1(189.23,20.32) v1(189.23,19.05) v1(189.23,17.78) v1(189.23,16.51) v1(189.23,15.24) v1(190.5,21.59) v1(190.5,20.32) v1(190.5,19.05) v1(190.5,17.78) v1(190.5,16.51) v1(190.5,15.24) v1(191.77,21.59) v1(191.77,20.32) v1(191.77,19.05) v1(191.77,17.78) v1(191.77,16.51) v1(191.77,15.24) v1(193.04,22.86) v1(193.04,21.59) v1(193.04,20.32) v1(193.04,19.05) v1(193.04,17.78) v1(193.04,16.51) v1(193.04,15.24) v1(194.31,22.86) v1(194.31,21.59) v1(194.31,20.32) v1(194.31,19.05) v1(194.31,17.78) v1(194.31,16.51) v1(194.31,15.24)
VDD_2P5V_PG_: length 4.2
  TOP w0.508: R36.2 162.57,24.13 162.23,24.48 U7.5
VDD_2P5V_REG_ENABLE_: length 7.5
  TOP w0.508: U7.1 154.49,25.39 R35.1 149.24,25.39 J8.2
VDD_3P3V:
  vias: v1(110.49,36.83) v1(110.49,35.56) v1(110.49,34.29) v1(111.76,36.83) v1(111.76,35.56) v1(111.76,34.29) v1(113.03,36.83) v1(113.03,35.56) v1(113.03,34.29) v1(114.3,36.83) v1(114.3,35.56) v1(114.3,34.29) v1(115.57,36.83) v1(115.57,35.56) v1(115.57,34.29) v1(116.84,36.83) v1(116.84,35.56) v1(116.84,34.29) v1(118.11,36.83) v1(118.11,35.56) v1(118.11,34.29) v1(119.38,36.83) v1(119.38,35.56) v1(119.38,34.29) v1(120.65,36.83) v1(120.65,35.56) v1(120.65,34.29) v1(121.92,36.83) v1(121.92,35.56) v1(121.92,34.29) v1(147.96,22.23) v1(147.96,20.95) v1(147.96,19.68) v1(147.96,18.41) v1(147.96,17.14) v1(149.22,22.23) v1(149.22,20.95) v1(149.22,19.68) v1(149.22,18.41) v1(149.22,17.14) v1(150.5,22.23) v1(150.5,20.95) v1(150.5,19.68) v1(150.5,18.41) v1(150.5,17.14) v1(151.76,22.23) v1(151.76,20.95) v1(151.76,19.68) v1(151.76,18.41) v1(151.76,17.14) v1(153.03,22.23) v1(153.03,20.95) v1(153.03,19.68) v1(153.03,18.41) v1(153.03,17.14) v1(154.31,22.23) v1(154.31,20.95) v1(154.31,19.68) v1(154.31,18.41) v1(154.31,17.14)
VDD_3P3V_USB: length 6.5
  TOP w0.508: C33.2 87.63,35.56 v1(87,36.2) ; R25.2 v1(98.42,20.32)
  BOTTOM w0.254: U3.18 83.78,20.36 ; v1(87,20.32) 87.28,20.6 U3.11 ; U3.50 87.28,35.84 87,36.13 v1(87,36.2)
  BOTTOM w0.279: 83.78,20.36 v1(83.82,20.32)
  vias: v1(59.05,19.05) v1(59.05,17.78) v1(60.33,19.05) v1(60.33,17.78) v1(60.33,16.51) v1(87,19.05) v1(88.27,20.32) v1(88.27,19.05)
ADDR0_1: length 40
  TOP w0.183: v1(117.47,86.36) 117.6,86.49 R8.2 ; U1.D13 v2(92.13,65.4)
  ART04 w0.132: v1(117.47,86.36) 116.59,87.25 115.44,87.25 114.81,86.61 114.81,83.06 100.38,68.63 100.38,67.49 97.64,64.74 92.79,64.74 v2(92.13,65.4)
ADDR0_2: length 59.1
  TOP w0.183: R24.2 v1(85.85,86.49) ; U2.D13 v2(115.13,74.2)
  ART04 w0.132: v1(85.85,86.49) 87.25,85.09 102.87,85.09 105.41,87.63 105.41,88.9 106.68,90.17 113.28,90.17 115.19,88.27 118.62,88.27 120.27,86.61 120.27,85.47 112.01,77.21 112.01,75.82 112.9,74.93 114.4,74.93 v2(115.13,74.2)
ADDR1_1: length 43.3
  TOP w0.183: U1.E13 v2(90.53,65.4) ; R7.2 115.7,86.49 v1(115.57,86.36)
  ART04 w0.132: v2(90.53,65.4) 90.04,64.91 90.04,64.08 90.63,63.49 90.63,62.28 91.01,61.9 95.5,61.9 100.84,67.23 100.84,68.45 115.57,83.19 v1(115.57,86.36)
ADDR1_2: length 60
  TOP w0.183: R23.2 v1(87.76,86.49) ; U2.E13 v2(116.73,74.2)
  ART04 w0.132: v2(116.73,74.2) 117.57,73.36 120.85,73.36 121.79,74.3 121.79,87.42 119.8,89.41 115.57,89.41 113.28,91.69 90.68,91.69 87.76,88.77 v1(87.76,86.49)
AIN_B_0: length 7.2
  BOTTOM w0.203: J1.1 92.28,14.48 U3.1
AIN_B_1: length 13.1
  BOTTOM w0.203: U3.2 91.78,18.5 90.61,17.34 90.61,13.53 91.06,13.08 93.42,13.08 J1.2
ALL_DONE_N_1: length 24.8
  TOP w0.183: U1.D3 v2(92.13,74.2)
  ART02 w0.132: v2(92.13,74.2) 91.64,73.71 91.06,73.71 90.68,74.09 90.68,82.17 92.79,84.28 92.79,88.29 TP3.1
  ART04 w0.132: J17.1 96.65,90.25 TP3.1
ALL_DONE_N_2: length 39.2
  TOP w0.183: U2.D3 v2(115.13,65.4)
  ART04 w0.132: TP15.1 89.33,49.28 100.46,49.28 108.84,57.66 111.02,57.66 116.2,62.84 116.2,64.33 v2(115.13,65.4)
BOT_INTL_CABLE: length 31.7
  TOP w0.183: R43.1 158.24,50.29 v1(158.12,50.16) 156.34,48.39 156.34,47.07
  ART04 w0.132: U9.L28 153.01,69.75 155.56,67.2 155.56,57.26 154.69,56.39 154.69,49.91 155.32,49.28 157.23,49.28 v1(158.12,50.16)
BOT_INTL_HOST: length 32.6
  TOP w0.183: R39.1 v1(40.01,49.53) 40.01,47.19 J13.14
  ART04 w0.132: U8.L28 53.05,68.93 52.03,67.91 52.03,57.75 45.47,51.18 41.66,51.18 v1(40.01,49.53)
BOT_LPMODE_CABLE: length 31
  ART04 w0.132: J14.18 160.2,45.85 155.7,45.85 155.07,46.48 155.07,48.9 154.18,49.78 154.18,59.44 151.85,61.77 151.85,67.36 U9.L31
BOT_LPMODE_HOST: length 32.6
  ART04 w0.132: U8.L31 56,70.21 56,58.77 49.4,52.17 49.4,46.98 48.39,45.97 46.3,45.97 J13.18
BOT_MODPRSL_CABLE: length 39.3
  TOP w0.183: R44.1 155.7,50.29 v1(155.57,50.16) 153.8,48.39 J14.12 155.02,45.85 162.74,45.85 J14.20
  ART04 w0.132: v1(155.57,50.16) 156.59,51.18 156.59,56.56 155.9,57.25 155.9,69.27 154.41,70.76 U9.L27
BOT_MODPRSL_HOST: length 38.4
  TOP w0.183: R40.1 37.47,47.19 J13.12 38.81,45.85 46.53,45.85 J13.20
  ART04 w0.132: U8.L27 52.37,67.01 52.37,57.6 47.75,52.98 J13.20
BOT_MODSELL_CABLE: length 25.7
  ART04 w0.132: U9.L8 158.17,68.53 162.24,64.45 162.24,58.57 158.88,55.2 J14.16
BOT_MODSELL_HOST: length 41.1
  ART04 w0.132: U8.L8 54.13,71.33 54.69,71.88 55.24,71.88 56.38,70.75 56.38,58.54 49.83,51.99 49.83,46.78 48.64,45.59 44.15,45.59 J13.16
CAL_CLK_IN_1: length 72.8
  TOP w0.183: v2(91.59,78.08) 90.93,77.42 U1.E1 ; R34.2 108.08,53.85 v1(107.95,53.98)
  ART02 w0.132: v1(107.95,53.98) 113.92,53.98 125.81,65.86 125.81,74.27 120.14,79.93 93.45,79.93 v2(91.59,78.08)
CAL_CLK_OUT_1: length 30
  TOP w0.183: U2.E1 116.33,63.02 v2(117.09,62.26) ; v1(91.19,62.61) 90.93,62.87 U1.E15
  ART02 w0.132: v1(91.19,62.61) 91.54,62.26 v2(117.09,62.26)
CAL_CLK_OUT_2: length 48.7
  TOP w0.183: U2.E15 116.33,76.48 arc(116.27,76.81) v1(116.08,77.09)
  ART04 w0.132: TP7.1 92.91,88.27 96.14,88.27 97.54,86.87 104.01,86.87 105.03,87.88 105.03,89.15 106.55,90.68 113.28,90.68 115.32,88.65 119.13,88.65 120.78,87 120.78,81.79 v1(116.08,77.09)
DM: length 83.1
  TOP w0.203: R28.2 v1(30.48,17.14)
  ART04 w0.132: v1(30.48,17.14) 30.96,17.14 31.18,16.93 31.18,16.15 31.59,15.74 33.25,15.74 36.46,18.95 36.46,25.55 38.72,27.81 72.13,27.81 81.4,37.08 87.89,37.08 89.97,35 90.16,34.8 90.16,32.25 90.47,31.95 91.52,31.95 91.67,31.8 91.67,31.54 91.52,31.38 v1(91.38,31.38)
  BOTTOM w0.203: U3.64 93.51,31.44 93.21,31.74 91.74,31.74 v1(91.38,31.38)
DP: length 83.1
  TOP w0.203: v1(31.75,17.14) R29.2 32.64,16.38 R30.1
  ART04 w0.132: v1(91.38,32.5) 91.38,32.36 91.23,32.21 90.58,32.21 90.42,32.36 90.42,34.91 90.15,35.18 88,37.34 81.29,37.34 72.02,28.07 38.61,28.07 36.2,25.66 36.2,19.06 33.15,16 31.69,16 31.44,16.26 31.44,16.83 v1(31.75,17.14)
  BOTTOM w0.203: v1(91.38,32.5) 91.74,32.15 93.21,32.15 93.51,32.44 U3.62
EN_SMB_1: length 75.7
  TOP w0.183: U1.E3 v2(91.33,74.2)
  ART02 w0.132: v2(91.33,74.2) 91.01,74.52 91.01,78.54 92.94,80.47 120.33,80.47 126.31,74.48 126.31,65.65 115.06,54.4 J21.2
EN_SMB_2: length 33.1
  TOP w0.183: v2(115.93,65.4) 116.33,65.8 U2.E3
  ART04 w0.132: J20.2 95.17,48.77 100.67,48.77 109.05,57.15 111.03,57.15 116.59,62.71 116.59,64.75 v2(115.93,65.4)
GPIO0_I2C_SDA: length 28.2
  ART09 w0.132: J3.4 67.31,38.1 v1(85.09,38.1)
  BOTTOM w0.183: v1(85.09,38.1) 85.28,37.91 U3.46
GPIO1_I2C_SCL: length 33.8
  ART09 w0.132: v1(87,38.1) 86.11,37.21 65.66,37.21 J3.3
  BOTTOM w0.183: v1(87,38.1) 85.78,36.88 U3.47
GPIO2_SPI_SCLK: length 18.9
  ART04 w0.132: v1(85.09,33.66) 82.55,31.11 78.61,31.11 72.34,24.84 J15.13
  BOTTOM w0.183: v1(85.09,33.66) 84.78,33.97 U3.45
GPIO3_PWM2: length 13.2
  ART04 w0.132: v1(77.47,28.57) 74.68,25.78 74.68,23.52 J15.11
  BOTTOM w0.203: U3.33 78.97,29.44 78.11,28.57 v1(77.47,28.57)
GPIO4_UART_TXD: length 25.6
  ART04 w0.132: v1(86.36,32.38) 84.07,30.1 79.12,30.1 78.11,29.08 78.11,28.32 75.44,25.65 75.44,22.48 72.34,19.38 J15.9
  BOTTOM w0.183: U3.51 87.78,34.16 87.31,33.7 87.31,33.34 v1(86.36,32.38)
GPIO5_UART_RXD: length 28.6
  ART04 w0.132: v1(88.27,33.66) 88.27,32.89 84.84,29.46 79.38,29.46 78.74,28.83 78.74,26.67 76.71,24.64 76.71,22.1 74.22,19.61 74.22,17.98 J15.7
  BOTTOM w0.203: U3.52 88.28,33.67 v1(88.27,33.66)
GPIO6_PWM1: length 18.1
  ART04 w0.132: v1(79.38,27.3) 79.38,26.04 77.85,24.51 77.85,22.35 74.85,19.35 74.85,16.08 J15.5
  BOTTOM w0.203: U3.29 79.51,27.44 v1(79.38,27.3)
GPIO7_PWM0: length 17.6
  ART04 w0.132: J15.3 76.14,14.82 76.14,18.86 79.38,22.1 v1(79.38,24.13)
  BOTTOM w0.203: U3.23 79.69,24.44 v1(79.38,24.13)
GPIO8_ADC3: length 28.5
  ART04 w0.132: J15.1 85.7,8.48 89.53,12.32 89.53,19.05 v1(90.81,20.32)
  BOTTOM w0.203: v1(90.81,20.32) 90.78,20.35 U3.4
GPIO9_ADC2: length 23.9
  ART09 w0.132: J15.14 71.04,22.48 79.5,22.48 80.64,23.62 90.04,23.62 v1(90.81,22.86)
  BOTTOM w0.203: U3.3 91.28,22.39 v1(90.81,22.86)
GPIO10_VEREFN: length 20.5
  ART09 w0.132: J15.12 70.92,20.07 78.23,20.07 80.26,22.1 86.23,22.1 v1(87,22.86)
  BOTTOM w0.183: v1(87,22.86) 87.78,22.08 U3.10
GPIO11_VEREFP: length 24
  TOP w0.183: v1(88.27,22.86) 88.14,22.73 C29.2
  ART09 w0.132: J15.10 71.04,17.4 76.71,17.4 80.64,21.34 86.74,21.34 v1(88.27,22.86)
  BOTTOM w0.203: U3.9 88.28,22.85 v1(88.27,22.86)
GPIO12_EFC0_CLOCK: length 13.9
  BOTTOM w0.203: U3.21 76.12,23.44 J5.2
INT_N: length 129
  TOP w0.183: v1(119.38,86.36) 119.51,86.49 R12.2 ; U2.F3 v2(117.53,65.4) ; U1.F3 v2(89.73,74.2)
  ART02 w0.132: J5.1 72.14,63.09 83.92,74.88 89.05,74.88 v2(89.73,74.2)
  ART04 w0.132: v2(89.73,74.2) 90.93,75.4 90.93,76.58 98.93,84.58 103,84.58 105.92,87.5 105.92,88.77 106.81,89.66 113.16,89.66 114.94,87.88 118.36,87.88 119.38,86.87 v1(119.38,86.36) 108.34,75.32 108.34,70.99 111.38,67.94 114.99,67.94 v2(117.53,65.4)
P2_1: length 18.6
  ART04 w0.132: J15.8 71.22,17.53 72.9,17.53 73.66,18.29 73.66,19.81 76.07,22.23 76.07,25.27 v1(78.11,27.3)
  BOTTOM w0.203: v1(78.11,27.3) 78.74,27.94 U3.30
P2_3: length 24.6
  ART04 w0.132: J15.6 71.04,12.32 72.77,12.32 75.44,14.99 75.44,19.05 78.61,22.23 78.61,24.51 80.01,25.91 80.01,27.94 v1(79.38,28.57)
  BOTTOM w0.203: U3.32 79.74,28.94 v1(79.38,28.57)
P2_5: length 29.2
  ART04 w0.132: v1(82.55,28.57) 80.77,26.8 80.77,22.48 76.83,18.54 76.83,13.59 73.03,9.78 71.04,9.78 J15.4
  BOTTOM w0.183: U3.34 81.82,29.94 82.55,29.21 v1(82.55,28.57)
PUR: length 88.6
  TOP w0.254: S1.3 31.33,20.32 33.02,20.32 33.9,19.44 S1.1 33.9,17.14 34.16,16.88 R30.2 v1(34.92,15.88)
  TOP w0.305: R32.2 29.08,18.08 S1.3
  ART04 w0.132: v1(34.92,15.88) 36.7,17.65 48.01,17.65 53.85,23.5 66.55,23.5 68.71,25.65 71.88,25.65 81.03,34.8 88.14,34.8 88.9,34.04 88.9,30.48 90.81,28.57 92.96,28.57 95.36,30.98 v1(95.36,31.75)
  BOTTOM w0.183: U3.63 95.17,31.94 v1(95.36,31.75)
QSFP_RESETL_CABLE: length 37.1
  ART04 w0.132: U9.U9 149.62,69.33 147.63,71.32 147.63,77.16 136.25,88.54 J25.4
  ART09 w0.132: U9.U9 153.65,69.33 154.31,69.98 156.46,69.98 157.11,69.33 U9.L9
QSFP_RESETL_HOST: length 98
  ART04 w0.132: J25.3 123.9,95.38 77.72,95.38 60.07,77.72 60.07,72.61 59.41,71.95 58.77,71.95 57.49,70.67 U8.U9
  ART09 w0.132: U8.L9 51.03,70.53 51.69,71.19 54.16,71.19 54.82,70.53 U8.U9
QSFP_SCL_CABLE: length 44.9
  ART04 w0.132: 175.9,46.99 174.62,45.72 172.21,45.72 171.7,46.23 171.7,57.4 158.18,70.93 U9.L11
  ART09 w0.132: U9.L11 153.76,70.93 153.19,70.36 152.53,70.36 151.96,70.93 U9.U11
QSFP_SCL_HOST: length 51.4
  ART04 w0.132: U8.L11 50.89,68.77 49.55,67.44 35.69,67.44 19.81,51.56 J23.2
  ART09 w0.132: U8.U11 56.8,68.93 56.19,69.54 54.74,69.54 54.13,68.93 U8.L11
QSFP_SDA_CABLE: length 39.5
  ART04 w0.132: J24.1 173.35,56.78 U9.L12
  ART09 w0.132: U9.U12 153.67,71.73 154.33,72.39 156.21,72.39 156.87,71.73 U9.L12
QSFP_SDA_HOST: length 51.2
  ART04 w0.132: U8.L12 35.32,68.13 17.27,50.07 J23.1
  ART09 w0.132: U8.L12 51.49,68.13 52.05,67.56 53.68,67.56 54.24,68.13 U8.U12
QSFP_VCC_3P3V:
  vias: v1(32.38,54.61) v1(32.38,53.34) v1(34.92,54.61) v1(34.92,53.34) v1(37.47,54.61) v1(37.47,53.34) v1(40.01,54.61) v1(40.01,53.34) v1(43.18,54.61) v1(43.18,53.34) v1(45.72,55.24) v1(45.72,53.98) v1(46.99,55.24) v1(47.03,53.94) v1(110.49,44.45) v1(110.49,43.18) v1(110.49,41.91) v1(111.76,44.45) v1(111.76,43.18) v1(111.76,41.91) v1(113.03,44.45) v1(113.03,43.18) v1(113.03,41.91) v1(114.3,44.45) v1(114.3,43.18) v1(114.3,41.91) v1(115.57,44.45) v1(115.57,43.18) v1(115.57,41.91) v1(116.84,44.45) v1(116.84,43.18) v1(116.84,41.91) v1(118.11,44.45) v1(118.11,43.18) v1(118.11,41.91) v1(119.38,44.45) v1(119.38,43.18) v1(119.38,41.91) v1(120.65,44.45) v1(120.65,43.18) v1(120.65,41.91) v1(121.92,44.45) v1(121.92,43.18) v1(121.92,41.91) v1(144.78,55.24) v1(146.05,55.24) v1(147.32,55.24) v1(147.32,53.98) v1(148.59,55.24) v1(148.59,53.98) v1(150.5,55.24) v1(150.5,53.98) v1(153.03,55.24) v1(153.03,53.98) v1(155.57,55.24) v1(155.57,53.98) v1(158.12,55.24) v1(158.12,53.98)
READ_EN_N_1: length 36.5
  TOP w0.183: U1.F13 v2(89.73,65.4)
  ART04 w0.132: J16.2 109.98,78.87 99.82,68.71 99.82,67.64 98.5,66.32 92.35,66.32 91.97,65.94 90.27,65.94 v2(89.73,65.4)
READ_EN_N_2: length 39.2
  TOP w0.183: U2.F13 v2(117.53,74.2)
  ART04 w0.132: v2(117.53,74.2) 118.26,74.93 120.14,74.93 121.28,76.07 121.28,87.21 119.46,89.03 115.44,89.03 113.28,91.19 103.94,91.19 J17.2
RXN0_CABLE_BOT: length 74.8
  TOP w0.16: U1.B1 v2(93.68,76.33)
  ART09 w0.109: U9.L18 157.94,76.26 arc(157.84,76.24) 157.76,76.31 157.69,76.42 157.52,76.73 arc(157.42,76.86) 157.29,76.96 arc(157.26,77) 157.23,77.03 arc(157.11,77.27) 157.07,77.52 157.07,77.72 arc(156.84,78.91) 156.17,79.91 154.87,81.21 arc(152.82,82.58) 150.41,83.06 125.14,83.06 arc(124.04,83.28) 123.11,83.9 arc(122.35,84.4) 121.46,84.58 108.84,84.58 arc(103.69,83.56) 99.32,80.64 98.59,79.91 arc(98.02,79.08) 97.79,78.11 arc(97.79,78.04) 97.79,77.98 arc(97.7,77.51) 97.43,77.11 96.52,76.2 arc(95.82,75.73) 94.99,75.56 93.51,75.56 arc(93.37,75.62) 93.31,75.77 93.31,75.9 arc(93.32,75.95) 93.35,75.99 v2(93.68,76.33)
